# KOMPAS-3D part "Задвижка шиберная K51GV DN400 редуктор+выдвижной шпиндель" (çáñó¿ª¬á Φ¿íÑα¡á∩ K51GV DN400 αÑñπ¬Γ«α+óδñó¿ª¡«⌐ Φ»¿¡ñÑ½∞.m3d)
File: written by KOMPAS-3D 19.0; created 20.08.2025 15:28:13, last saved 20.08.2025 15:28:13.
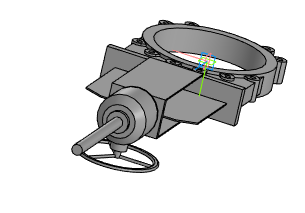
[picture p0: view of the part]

Document properties: Полное имя файла: Задвижка шиберная K51GV DN400 редуктор+выдвижной шпиндель.a3d

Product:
- Part/product: Задвижка шиберная K51GV DN400 редуктор+выдвижной шпиндель
    Масса: 156.874

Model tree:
1. Операция без истории:1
